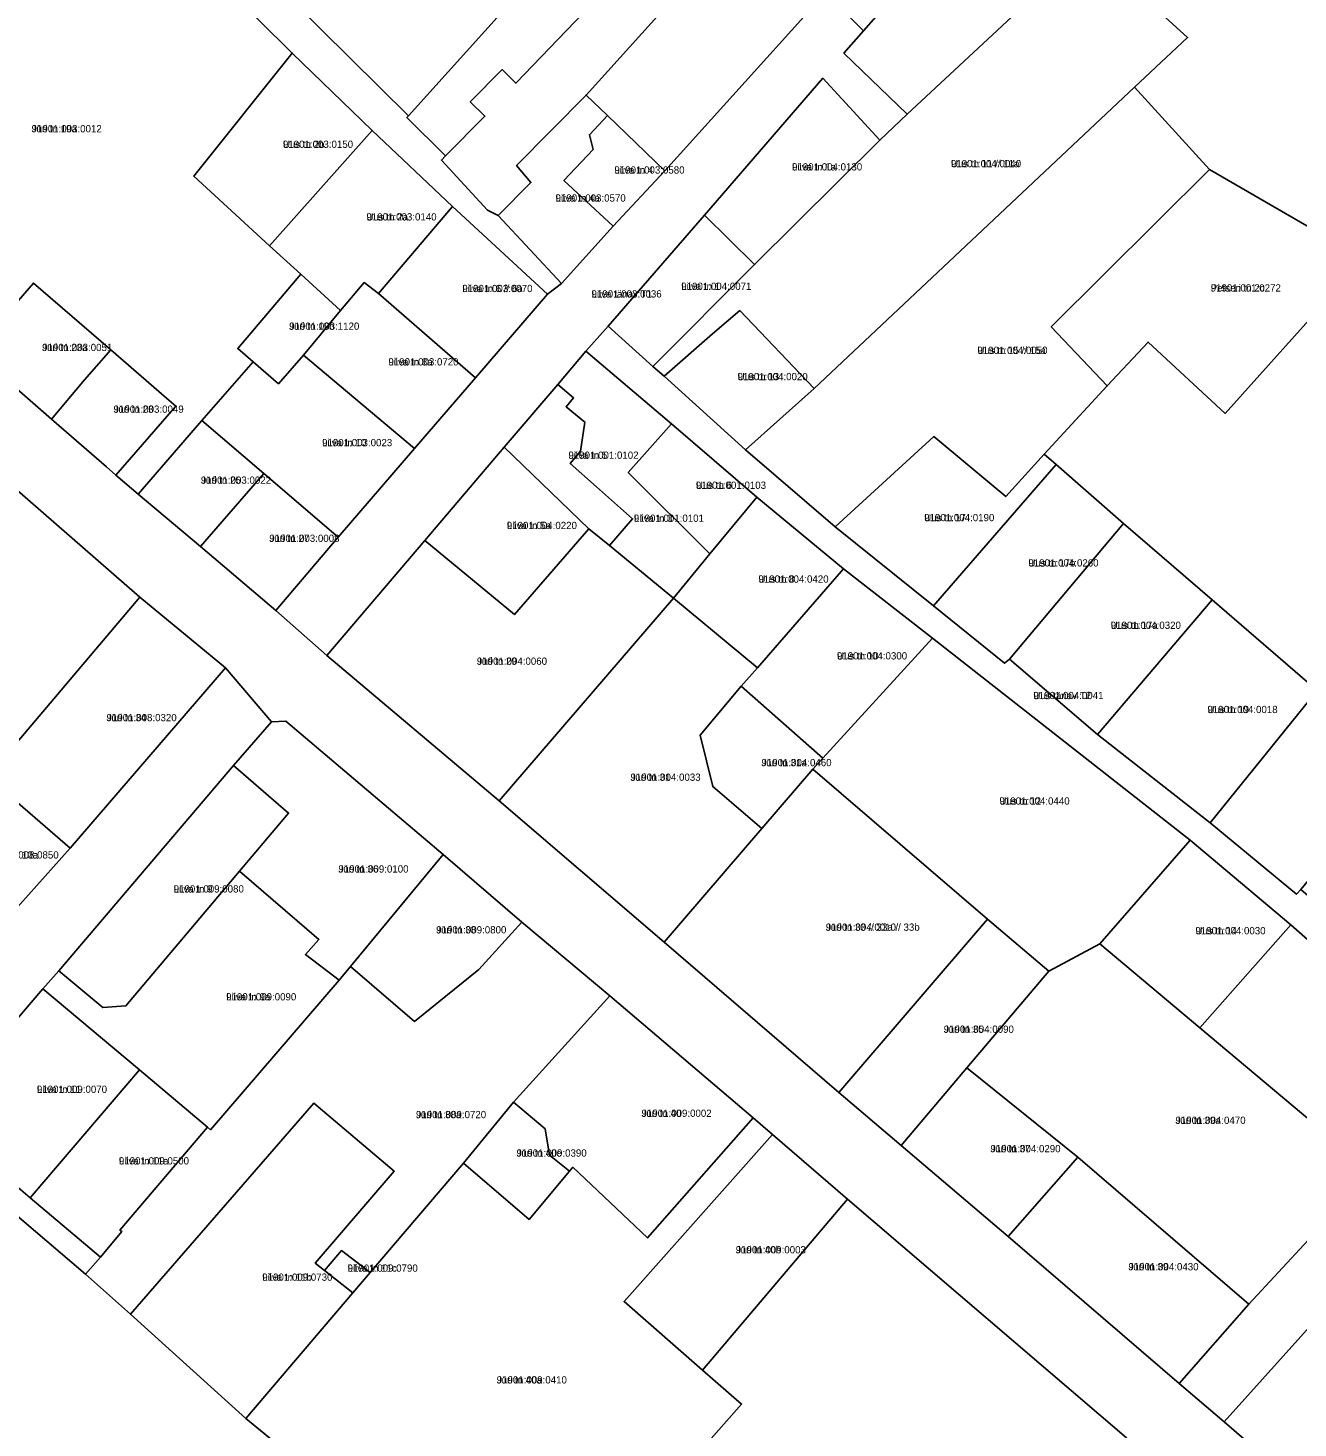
# Model space of a CAD drawing. Extents: x 675810 to 681273, y 6411190 to 6417565.
# Drawn here: x 678158 to 678420.5, y 6415256.1 to 6415545.6 of the extents above; entities that cross this region are included whole.
import ezdxf

# ---------------------------------------------------------------- set-up
doc = ezdxf.new("R2010")
doc.units = 0
for name, color, linetype in [('L_AADRESS', 7, 'Continuous'), ('PIIR', 7, 'Continuous'), ('TUNNUS', 7, 'Continuous')]:
    doc.layers.add(name, color=color, linetype=linetype)

msp = doc.modelspace()

# ---------------------------------------------------------------- linework, layer by layer
at = {"layer": 'PIIR'}
for points in [[(678434.11, 6415497.88), (678402.16, 6415516.32), (678386.72, 6415533.35), (678397.66, 6415543.62), (678376.95, 6415562.53), (678358.7, 6415576.94), (678330.66, 6415545.02), (678322.83, 6415552.96), (678348.36, 6415581.27), (678334.71, 6415599.8), (678330.39, 6415608.7), (678323.09, 6415618.36), (678304.36, 6415640.15), (678270.47, 6415679.59), (678288.98, 6415703.2), (678213.72, 6415768.23), (678276.58, 6415835.21)], [(678133.69, 6415553.59), (678176.04, 6415557.04), (678185.22, 6415567.57), (678212.62, 6415540.4), (678192.24, 6415514.99), (678207.91, 6415500.54), (678214.36, 6415494.68), (678201.34, 6415479.3), (678204.55, 6415476.57), (678193.95, 6415464.45), (678180.75, 6415449.2), (678176.17, 6415453.14), (678188.52, 6415467.41), (678186.61, 6415469.04), (678175.08, 6415479.02), (678159.11, 6415492.87), (678146.81, 6415478.68)], [(678146.81, 6415478.68), (678162.82, 6415464.74), (678174.18, 6415454.86), (678176.17, 6415453.14), (678180.75, 6415449.2), (678193.63, 6415438.41), (678209.19, 6415425.16), (678219.73, 6415415.84), (678255.38, 6415385.81), (678289.47, 6415356.54), (678325.56, 6415325.52), (678338.47, 6415314.51), (678360.57, 6415295.7), (678395.92, 6415265.33), (678405.25, 6415257.4), (678420.55, 6415244.19)], [(678385.04, 6415254.07), (678327.36, 6415303.43), (678311.89, 6415316.79), (678307.89, 6415320.24), (678278.25, 6415345.48), (678260.09, 6415360.73), (678243.78, 6415374.68), (678211.25, 6415402.27), (678208.34, 6415402.14), (678198.81, 6415413.28), (678181.09, 6415427.91), (678151.94, 6415453.26)]]:
    msp.add_lwpolyline(points, dxfattribs=at)
for points in [[(678098.17, 6415637.56), (678102.82, 6415642.96), (678171.75, 6415587.65), (678186.99, 6415575.28), (678192.63, 6415569.68), (678212.04, 6415550.8), (678212.55, 6415551.27), (678236.61, 6415527.43), (678236.29, 6415527.07), (678244.28, 6415519.15), (678243.42, 6415518.28), (678252.93, 6415507.94), (678255.14, 6415506.85), (678268.24, 6415492.75), (678265.34, 6415490.55), (678245.76, 6415508.69), (678229.11, 6415524.4), (678212.62, 6415540.4), (678185.22, 6415567.57), (678168, 6415581.41), (678135.27, 6415607.73)], [(678260.59, 6415554.09), (678268.24, 6415562), (678302.46, 6415597.15), (678323.09, 6415618.36), (678330.39, 6415608.7), (678258.82, 6415534.18), (678255.99, 6415536.99), (678249.4, 6415530.35), (678252.42, 6415527.35), (678244.28, 6415519.15), (678236.29, 6415527.07), (678236.61, 6415527.43)], [(678252.93, 6415507.94), (678243.42, 6415518.28), (678244.28, 6415519.15), (678252.42, 6415527.35), (678249.4, 6415530.35), (678255.99, 6415536.99), (678258.82, 6415534.18), (678330.39, 6415608.7), (678334.71, 6415599.8), (678273.32, 6415531.74), (678258.97, 6415517.14), (678261.93, 6415513.65), (678255.14, 6415506.85)], [(678289.62, 6415516.07), (678277.75, 6415527.48), (678273.32, 6415531.74), (678334.71, 6415599.8), (678348.36, 6415581.27), (678322.83, 6415552.96)], [(678222.25, 6415560.93), (678220.45, 6415562.77), (678229.77, 6415570.7), (678234.57, 6415566.31), (678240.82, 6415572.58), (678248.62, 6415581.15), (678268.24, 6415562), (678260.59, 6415554.09), (678236.61, 6415527.43), (678212.55, 6415551.27)], [(678358.7, 6415576.94), (678376.95, 6415562.53), (678339.73, 6415527.8), (678326.62, 6415540.38), (678330.66, 6415545.02)], [(678289.51, 6415473.6), (678287.12, 6415475.58), (678308.15, 6415496.68), (678334.02, 6415522.41), (678339.73, 6415527.8), (678376.95, 6415562.53), (678397.66, 6415543.62), (678386.72, 6415533.35), (678320.47, 6415471.09), (678305.14, 6415487.16), (678299.48, 6415482.33)], [(678322.83, 6415552.96), (678330.66, 6415545.02), (678326.62, 6415540.38), (678339.73, 6415527.8), (678334.02, 6415522.41), (678322.24, 6415535.22), (678297.78, 6415506.92), (678277.87, 6415483.96), (678273.27, 6415478.75), (678267.51, 6415471.9), (678256.4, 6415458.9), (678239.98, 6415439.6), (678219.73, 6415415.84), (678209.19, 6415425.16), (678222.13, 6415440.3), (678237.88, 6415458.68), (678250.46, 6415473.29), (678265.34, 6415490.55), (678268.24, 6415492.75), (678278.92, 6415504.59), (678289.62, 6415516.07)], [(678207.91, 6415500.54), (678192.24, 6415514.99), (678212.62, 6415540.4), (678229.11, 6415524.4)], [(678334.02, 6415522.41), (678308.15, 6415496.68), (678297.78, 6415506.92), (678322.24, 6415535.22)], [(678324.85, 6415442.44), (678306.27, 6415458.37), (678320.47, 6415471.09), (678386.72, 6415533.35), (678402.16, 6415516.32), (678369.49, 6415483.78), (678381.04, 6415471.59), (678368.05, 6415457.5), (678360.07, 6415448.72), (678345.2, 6415461.13)], [(678255.14, 6415506.85), (678261.93, 6415513.65), (678258.97, 6415517.14), (678273.32, 6415531.74), (678277.75, 6415527.48), (678274.02, 6415523.53), (678274.78, 6415520.5), (678268.76, 6415514.04), (678278.92, 6415504.59), (678268.24, 6415492.75)], [(678268.76, 6415514.04), (678274.78, 6415520.5), (678274.02, 6415523.53), (678277.75, 6415527.48), (678289.62, 6415516.07), (678278.92, 6415504.59)], [(678230.4, 6415490.68), (678227.48, 6415492.96), (678222.59, 6415487.2), (678214.36, 6415494.68), (678207.91, 6415500.54), (678229.11, 6415524.4), (678245.76, 6415508.69)], [(678402.16, 6415516.32), (678434.11, 6415497.88), (678405.4, 6415465.9), (678389.48, 6415480.64), (678381.04, 6415471.59), (678369.49, 6415483.78)], [(678250.46, 6415473.29), (678230.4, 6415490.68), (678245.76, 6415508.69), (678265.34, 6415490.55)], [(678297.78, 6415506.92), (678308.15, 6415496.68), (678287.12, 6415475.58), (678277.87, 6415483.96)], [(678434.11, 6415497.88), (678529.76, 6415416.4), (678497.75, 6415379.78), (678473.98, 6415399.41), (678456.97, 6415380.5), (678442.3, 6415393.23), (678424.47, 6415408.59), (678402.71, 6415427.34), (678384.39, 6415443.11), (678370.48, 6415455.37), (678368.05, 6415457.5), (678381.04, 6415471.59), (678389.48, 6415480.64), (678405.4, 6415465.9)], [(678159.11, 6415492.87), (678175.08, 6415479.02), (678169.65, 6415472.82), (678162.82, 6415464.74), (678146.81, 6415478.68)], [(678222.59, 6415487.2), (678214.91, 6415477.93), (678209.76, 6415472.03), (678204.55, 6415476.57), (678201.34, 6415479.3), (678214.36, 6415494.68)], [(678214.91, 6415477.93), (678222.59, 6415487.2), (678227.48, 6415492.96), (678230.4, 6415490.68), (678250.46, 6415473.29), (678237.88, 6415458.68)], [(678306.27, 6415458.37), (678289.51, 6415473.6), (678299.48, 6415482.33), (678305.14, 6415487.16), (678320.47, 6415471.09)], [(678273.27, 6415478.75), (678277.87, 6415483.96), (678287.12, 6415475.58), (678289.51, 6415473.6), (678306.27, 6415458.37), (678324.85, 6415442.44), (678345.13, 6415426.1), (678359.84, 6415414.24), (678360.85, 6415415.07), (678379.07, 6415399.51), (678402.32, 6415381.22), (678420.16, 6415366.53), (678421.09, 6415367.45), (678444.52, 6415347.27), (678458.78, 6415334.97), (678453.58, 6415329.69), (678419.02, 6415360.14), (678398.21, 6415377.65), (678344.96, 6415419.46), (678326.53, 6415433.78), (678308.66, 6415448.56), (678290.99, 6415463.75)], [(678175.08, 6415479.02), (678186.61, 6415469.04), (678188.52, 6415467.41), (678176.17, 6415453.14), (678174.18, 6415454.86), (678162.82, 6415464.74), (678169.65, 6415472.82)], [(678214.91, 6415477.93), (678237.88, 6415458.68), (678222.13, 6415440.3), (678206.71, 6415453.51), (678193.95, 6415464.45), (678204.55, 6415476.57), (678209.76, 6415472.03)], [(678267.51, 6415471.9), (678273.27, 6415478.75), (678290.99, 6415463.75), (678282.06, 6415453.67), (678298.89, 6415436.87), (678291.39, 6415427.7), (678278.17, 6415438.59), (678282.96, 6415444.11), (678275.48, 6415450.71), (678270.06, 6415455.52), (678272.21, 6415458.13), (678273.08, 6415464.12), (678269.2, 6415467.29), (678270.76, 6415469.12)], [(678273.93, 6415442.06), (678256.4, 6415458.9), (678267.51, 6415471.9), (678270.76, 6415469.12), (678269.2, 6415467.29), (678273.08, 6415464.12), (678272.21, 6415458.13), (678270.06, 6415455.52), (678275.48, 6415450.71), (678282.96, 6415444.11), (678278.17, 6415438.59)], [(678193.95, 6415464.45), (678206.71, 6415453.51), (678193.63, 6415438.41), (678180.75, 6415449.2)], [(678298.89, 6415436.87), (678282.06, 6415453.67), (678290.99, 6415463.75), (678308.66, 6415448.56)], [(678366.36, 6415450.61), (678345.13, 6415426.1), (678324.85, 6415442.44), (678345.2, 6415461.13), (678360.07, 6415448.72), (678368.05, 6415457.5), (678370.48, 6415455.37)], [(678256.4, 6415458.9), (678273.93, 6415442.06), (678258.54, 6415424.3), (678239.98, 6415439.6)], [(678565.67, 6415457.65), (678584.63, 6415437.83), (678571.47, 6415422.91), (678577.83, 6415417.22), (678585.87, 6415405.7), (678566.01, 6415382.6), (678560.85, 6415376.6), (678533.42, 6415400.18), (678488.18, 6415348.7), (678464.2, 6415322.7), (678452.22, 6415309.34), (678433.25, 6415288.62), (678405.25, 6415257.4), (678395.92, 6415265.33), (678410.29, 6415281.72), (678428.69, 6415301.59), (678442, 6415316.83), (678453.58, 6415329.69), (678458.78, 6415334.97), (678482.4, 6415362.13), (678497.75, 6415379.78), (678529.76, 6415416.4)], [(678360.85, 6415415.07), (678359.84, 6415414.24), (678345.13, 6415426.1), (678366.36, 6415450.61), (678370.48, 6415455.37), (678384.39, 6415443.11)], [(678138.38, 6415437.18), (678151.94, 6415453.26), (678181.09, 6415427.91), (678149.63, 6415390.76), (678134.18, 6415372.53), (678111.15, 6415391.61), (678100.19, 6415378.37), (678092.79, 6415384.48), (678090.01, 6415386.76), (678096.98, 6415393.88), (678089.85, 6415400.89), (678082.84, 6415393.75), (678077.52, 6415398.96), (678080.12, 6415402.19), (678105.17, 6415431.39), (678131.41, 6415442.85)], [(678193.63, 6415438.41), (678206.71, 6415453.51), (678222.13, 6415440.3), (678209.19, 6415425.16)], [(678326.53, 6415433.78), (678308.76, 6415413.27), (678291.39, 6415427.7), (678298.89, 6415436.87), (678308.66, 6415448.56)], [(678402.71, 6415427.34), (678379.07, 6415399.51), (678360.85, 6415415.07), (678384.39, 6415443.11)], [(678219.73, 6415415.84), (678239.98, 6415439.6), (678258.54, 6415424.3), (678273.93, 6415442.06), (678278.17, 6415438.59), (678291.39, 6415427.7), (678255.38, 6415385.81)], [(678305.42, 6415409.48), (678308.76, 6415413.27), (678326.53, 6415433.78), (678344.96, 6415419.46), (678322.26, 6415394.63)], [(678149.63, 6415390.76), (678181.09, 6415427.91), (678198.81, 6415413.28), (678166.7, 6415375.98)], [(678255.38, 6415385.81), (678291.39, 6415427.7), (678308.76, 6415413.27), (678305.42, 6415409.48), (678296.9, 6415399.36), (678299.52, 6415388.75), (678309.64, 6415380.05), (678289.47, 6415356.54)], [(678402.71, 6415427.34), (678424.47, 6415408.59), (678402.32, 6415381.22), (678379.07, 6415399.51)], [(678322.26, 6415394.63), (678344.96, 6415419.46), (678398.21, 6415377.65), (678379.53, 6415356.26), (678368.95, 6415350.58), (678356.32, 6415361.32), (678320.23, 6415392.34)], [(678198.81, 6415413.28), (678208.34, 6415402.14), (678200.49, 6415393.13), (678164.36, 6415350.68), (678161.07, 6415346.92), (678138.62, 6415320.63), (678158.43, 6415303.7), (678172.98, 6415291.47), (678169.9, 6415287.94), (678135.46, 6415317.19), (678080.44, 6415252.61), (678073.13, 6415244.08), (678060, 6415228.7), (678047.94, 6415239.03), (678062.66, 6415256.13), (678076.36, 6415272.05), (678099.99, 6415298.95), (678104.07, 6415303.65), (678126.77, 6415330.16), (678145.87, 6415352.47), (678149.44, 6415356.72), (678166.7, 6415375.98)], [(678299.52, 6415388.75), (678296.9, 6415399.36), (678305.42, 6415409.48), (678322.26, 6415394.63), (678320.23, 6415392.34), (678309.64, 6415380.05)], [(678442.3, 6415393.23), (678421.09, 6415367.45), (678420.16, 6415366.53), (678402.32, 6415381.22), (678424.47, 6415408.59)], [(678211.84, 6415383.25), (678200.49, 6415393.13), (678208.34, 6415402.14), (678211.25, 6415402.27), (678243.78, 6415374.68), (678222.32, 6415348.74), (678215.31, 6415354), (678218.12, 6415357.1), (678201.71, 6415371.26)], [(678166.7, 6415375.98), (678149.44, 6415356.72), (678132.96, 6415371.08), (678134.18, 6415372.53), (678149.63, 6415390.76)], [(678173.48, 6415343.08), (678164.36, 6415350.68), (678200.49, 6415393.13), (678211.84, 6415383.25), (678201.71, 6415371.26), (678178.24, 6415343.4)], [(678289.47, 6415356.54), (678309.64, 6415380.05), (678320.23, 6415392.34), (678356.32, 6415361.32), (678325.56, 6415325.52)], [(678379.53, 6415356.26), (678398.21, 6415377.65), (678419.02, 6415360.14), (678400.18, 6415338.89)], [(678260.09, 6415360.73), (678251.18, 6415350.91), (678237.89, 6415340.19), (678224.62, 6415351.54), (678243.78, 6415374.68)], [(678161.07, 6415346.92), (678164.36, 6415350.68), (678173.48, 6415343.08), (678178.24, 6415343.4), (678201.71, 6415371.26), (678218.12, 6415357.1), (678215.31, 6415354), (678222.32, 6415348.74), (678195.7, 6415317.8), (678195.11, 6415318.29), (678181.04, 6415330.16)], [(678222.32, 6415348.74), (678224.62, 6415351.54), (678237.89, 6415340.19), (678251.18, 6415350.91), (678260.09, 6415360.73), (678278.25, 6415345.48), (678258.34, 6415323.5), (678248, 6415310.9), (678228.71, 6415288.25), (678222.77, 6415292.79), (678219.27, 6415288.71), (678217.35, 6415290.22), (678233.69, 6415309.2), (678217.07, 6415323.3), (678179.14, 6415279.62), (678169.9, 6415287.94), (678172.98, 6415291.47), (678177.35, 6415296.75), (678176.99, 6415297.05), (678195.11, 6415318.29), (678195.7, 6415317.8)], [(678338.47, 6415314.51), (678325.56, 6415325.52), (678356.32, 6415361.32), (678368.95, 6415350.58), (678352.05, 6415330.57)], [(678400.18, 6415338.89), (678419.02, 6415360.14), (678453.58, 6415329.69), (678442, 6415316.83), (678433.19, 6415322.87), (678427.17, 6415316.21)], [(678375, 6415312.11), (678352.05, 6415330.57), (678368.95, 6415350.58), (678379.53, 6415356.26), (678400.18, 6415338.89), (678427.17, 6415316.21), (678423.18, 6415311.45), (678428.69, 6415301.59), (678410.29, 6415281.72)], [(678158.43, 6415303.7), (678138.62, 6415320.63), (678161.07, 6415346.92), (678181.04, 6415330.16)], [(678278.25, 6415345.48), (678307.89, 6415320.24), (678286, 6415295.42), (678270.63, 6415310.04), (678269.93, 6415309.22), (678265.75, 6415312.56), (678264.85, 6415317.98), (678258.34, 6415323.5)], [(678158.43, 6415303.7), (678181.04, 6415330.16), (678195.11, 6415318.29), (678176.99, 6415297.05), (678177.35, 6415296.75), (678172.98, 6415291.47)], [(678360.57, 6415295.7), (678338.47, 6415314.51), (678352.05, 6415330.57), (678375, 6415312.11)], [(678179.14, 6415279.62), (678217.07, 6415323.3), (678233.69, 6415309.2), (678217.35, 6415290.22), (678219.27, 6415288.71), (678225.15, 6415284.07), (678203, 6415258.09)], [(678258.34, 6415323.5), (678264.85, 6415317.98), (678265.75, 6415312.56), (678269.93, 6415309.22), (678261.57, 6415299.25), (678248, 6415310.9)], [(678286, 6415295.42), (678307.89, 6415320.24), (678311.89, 6415316.79), (678281.19, 6415282.24), (678297.38, 6415268.09), (678305.48, 6415261.06), (678291.98, 6415245.77), (678267.33, 6415217.4), (678261.23, 6415210.39), (678249.44, 6415220.06), (678203, 6415258.09), (678225.15, 6415284.07), (678228.71, 6415288.25), (678248, 6415310.9), (678261.57, 6415299.25), (678269.93, 6415309.22), (678270.63, 6415310.04)], [(678135.46, 6415317.19), (678169.9, 6415287.94), (678179.14, 6415279.62), (678203, 6415258.09), (678249.44, 6415220.06), (678215.92, 6415178.31), (678209.26, 6415184.48), (678200.6, 6415192.59), (678191.04, 6415201.02), (678168.78, 6415218.8), (678152.86, 6415231.73), (678132.93, 6415246.21), (678116.26, 6415223.58), (678093.94, 6415241.63), (678080.44, 6415252.61)], [(678311.89, 6415316.79), (678327.36, 6415303.43), (678297.38, 6415268.09), (678281.19, 6415282.24)], [(678395.92, 6415265.33), (678360.57, 6415295.7), (678375, 6415312.11), (678410.29, 6415281.72)], [(678297.38, 6415268.09), (678327.36, 6415303.43), (678385.04, 6415254.07), (678340.98, 6415205.87), (678291.98, 6415245.77), (678305.48, 6415261.06)], [(678219.27, 6415288.71), (678222.77, 6415292.79), (678228.71, 6415288.25), (678225.15, 6415284.07)], [(678405.25, 6415257.4), (678433.25, 6415288.62), (678448.41, 6415276.29), (678439.58, 6415266.25), (678433.48, 6415259.07), (678420.55, 6415244.19)]]:
    msp.add_lwpolyline(points, close=True, dxfattribs=at)

# ---------------------------------------------------------------- texts
at = {"layer": 'L_AADRESS'}
for s, p in [('Jüri tn 19a', (678158.73, 6415524.03)), ('Uus tn 2b', (678210.68, 6415520.81)), ('Uus tn 11 // 11a', (678348.75, 6415516.81)), ('Liiva tn 4', (678279.19, 6415515.49)), ('Liiva tn 1a', (678315.9, 6415516.14)), ('Liiva tn 4a', (678267.03, 6415509.7)), ('Uus tn 2a', (678227.94, 6415505.8)), ('Liiva tn 6 // 6a', (678247.76, 6415490.99)), ('Liiva tn 1', (678293.01, 6415491.45)), ('Petseri tn 2c', (678402.44, 6415491.11)), ('Liiva tänav T1', (678274.46, 6415489.87)), ('Jüri tn 19b', (678211.97, 6415483.2)), ('Jüri tn 23a', (678160.91, 6415478.8)), ('Uus tn 15 // 15a', (678354.21, 6415478.2)), ('Liiva tn 8a', (678232.48, 6415475.82)), ('Uus tn 13', (678304.65, 6415472.77)), ('Jüri tn 23', (678175.67, 6415466.04)), ('Liiva tn 10', (678218.77, 6415459.12)), ('Liiva tn 5', (678269.68, 6415456.52)), ('Jüri tn 25', (678193.73, 6415451.36)), ('Uus tn 6', (678296.03, 6415450.31)), ('Liiva tn 5a', (678256.95, 6415441.99)), ('Liiva tn 3', (678283.2, 6415443.49)), ('Uus tn 17', (678343.22, 6415443.62)), ('Jüri tn 27', (678207.87, 6415439.34)), ('Uus tn 17b', (678364.76, 6415434.25)), ('Uus tn 8', (678308.96, 6415430.91)), ('Uus tn 17a', (678381.78, 6415421.35)), ('Jüri tn 29', (678250.77, 6415413.93)), ('Uus tn 10', (678325.19, 6415415.03)), ('Uus tänav T2', (678365.78, 6415406.83)), ('Uus tn 19', (678401.77, 6415403.94)), ('Jüri tn 34', (678174.22, 6415402.26)), ('Jüri tn 31a', (678309.58, 6415392.96)), ('Jüri tn 31', (678282.51, 6415389.94)), ('Uus tn 12', (678358.78, 6415385.02)), ('Liiva tn 10a', (678149.83, 6415373.87)), ('Jüri tn 36', (678222.14, 6415370.96)), ('Liiva tn 9', (678188.1, 6415366.84)), ('Jüri tn 38', (678242.36, 6415358.38)), ('Jüri tn 33 // 33a // 33b', (678322.89, 6415358.93)), ('Uus tn 14', (678399.28, 6415358.2)), ('Liiva tn 9a', (678198.94, 6415344.53)), ('Jüri tn 35', (678347.26, 6415337.83)), ('Liiva tn 11', (678159.83, 6415325.4)), ('Jüri tn 38a', (678238.18, 6415320.18)), ('Jüri tn 40', (678284.79, 6415320.45)), ('Jüri tn 39a', (678395.15, 6415318.99)), ('Jüri tn 40c', (678258.96, 6415312.23)), ('Jüri tn 37', (678356.91, 6415313.13)), ('Liiva tn 11a', (678176.77, 6415310.61)), ('Jüri tn 40b', (678304.27, 6415292.22)), ('Liiva tn 11c', (678224.05, 6415288.43)), ('Jüri tn 39', (678385.43, 6415288.72)), ('Liiva tn 11b', (678206.41, 6415286.56)), ('Jüri tn 40a', (678254.87, 6415265.32))]:
    msp.add_text(s, height=1.5, dxfattribs=at).set_placement(p)
at = {"layer": 'TUNNUS'}
for s, p in [('91901:003:0012', (678158.73, 6415524.03)), ('91901:003:0150', (678210.68, 6415520.81)), ('91901:004:0040', (678348.75, 6415516.81)), ('91901:003:0580', (678279.19, 6415515.49)), ('91901:004:0130', (678315.9, 6415516.14)), ('91901:003:0570', (678267.03, 6415509.7)), ('91901:003:0140', (678227.94, 6415505.8)), ('91901:003:0070', (678247.76, 6415490.99)), ('91901:004:0071', (678293.01, 6415491.45)), ('91901:001:0272', (678402.44, 6415491.11)), ('91901:003:0036', (678274.46, 6415489.87)), ('91901:003:1120', (678211.97, 6415483.2)), ('91901:003:0051', (678160.91, 6415478.8)), ('91901:004:0050', (678354.21, 6415478.2)), ('91901:003:0720', (678232.48, 6415475.82)), ('91901:004:0020', (678304.65, 6415472.77)), ('91901:003:0049', (678175.67, 6415466.04)), ('91901:003:0023', (678218.77, 6415459.12)), ('91901:001:0102', (678269.68, 6415456.52)), ('91901:003:0022', (678193.73, 6415451.36)), ('91901:001:0103', (678296.03, 6415450.31)), ('91901:004:0220', (678256.95, 6415441.99)), ('91901:001:0101', (678283.2, 6415443.49)), ('91901:004:0190', (678343.22, 6415443.62)), ('91901:003:0008', (678207.87, 6415439.34)), ('91901:004:0260', (678364.76, 6415434.25)), ('91901:004:0420', (678308.96, 6415430.91)), ('91901:004:0320', (678381.78, 6415421.35)), ('91901:004:0060', (678250.77, 6415413.93)), ('91901:004:0300', (678325.19, 6415415.03)), ('91901:004:0041', (678365.78, 6415406.83)), ('91901:004:0018', (678401.77, 6415403.94)), ('91901:008:0320', (678174.22, 6415402.26)), ('91901:004:0460', (678309.58, 6415392.96)), ('91901:004:0033', (678282.51, 6415389.94)), ('91901:004:0440', (678358.78, 6415385.02)), ('91901:008:0850', (678149.83, 6415373.87)), ('91901:009:0100', (678222.14, 6415370.96)), ('91901:009:0080', (678188.1, 6415366.84)), ('91901:009:0800', (678242.36, 6415358.38)), ('91901:004:0010', (678322.89, 6415358.93)), ('91901:004:0030', (678399.28, 6415358.2)), ('91901:009:0090', (678198.94, 6415344.53)), ('91901:004:0090', (678347.26, 6415337.83)), ('91901:009:0070', (678159.83, 6415325.4)), ('91901:009:0720', (678238.18, 6415320.18)), ('91901:009:0002', (678284.79, 6415320.45)), ('91901:004:0470', (678395.15, 6415318.99)), ('91901:009:0390', (678258.96, 6415312.23)), ('91901:004:0290', (678356.91, 6415313.13)), ('91901:009:0500', (678176.77, 6415310.61)), ('91901:009:0003', (678304.27, 6415292.22)), ('91901:009:0790', (678224.05, 6415288.43)), ('91901:004:0430', (678385.43, 6415288.72)), ('91901:009:0730', (678206.41, 6415286.56)), ('91901:009:0410', (678254.87, 6415265.32))]:
    msp.add_text(s, height=1.5, dxfattribs=at).set_placement(p)

doc.saveas('drawing.dxf')
